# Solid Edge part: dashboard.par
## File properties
Author: Mac
Template: Normal.par
Last saved by: Mac
Revision: 6
Application: Solid Edge
Material: Epoxy, cast rigid
Face Style: Model Default
Fill Style: ANSI34(Plastic)
Virtual Style: Shiny resin yellow
Coef. of Thermal Exp: 5.9e-05
Thermal Conductivity: 2.1
Specific Heat: 0.0
Modulus of Elasticity: 3102640650.0
Poission's Ratio: 0.37
Yield Stress: 65500191.5
Ultimate Stress: 0.0
Elongation: 0.0
Density: 1300,000 kg/m^3
Accuracy: 0,990
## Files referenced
..\Asm16.asm
AC:\Documents and Settings\Mac\Desktop\ihu\Copy of paat4\Asm16.asm
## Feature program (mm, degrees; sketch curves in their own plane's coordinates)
sketch for "unnamed Protrusion 1" plane through (0, 0, 0) normal (0, 0, 1) x-axis (1, 0, 0)
  line (0, 0) -> (0, 27.8842)
  line (0, 27.8842) -> (0.9634, 27.8296)
  line (0.9634, 27.8296) -> (0.9634, 27.7356)
  line (17.9828, 26.6287) -> (17.9828, 25.9766)
  bspline degree 3 poles (17.9828, 25.9766) (24.7445, 25.4284) (31.4935, 24.7435) (38.2179, 23.8654) knots 0 1 multiplicities 4 4
  bspline degree 3 poles (38.2179, 23.8654) (40.5774, 20.624) (42.3706, 16.8932) (43.6319, 13.0202) (43.9649, 11.9978) (44.2696, 10.9289) (44.8221, 8.7743) (45.0694, 7.6895) (45.511, 5.5057) (45.7053, 4.4074) (45.87, 3.3016) (46.0334, 2.2045) (46.1675, 1.1039) (46.2626, 0) knots 0 0.5088 0.5836 0.6583 0.7331 1 multiplicities 4 3 2 2 3 4
  line (0, 0) -> (46.2626, 0)
extrude "unnamed Protrusion 1" add finite 17.53 along +normal
sketch for "unnamed Cutout 1" plane through (23.1313, 0, 8.765) normal (0, -1, 0) x-axis (1, 0, 0)
  line (-21.6003, 8.735) -> (-23.1313, -8.765)
  line (-23.1313, -8.765) -> (-27.6404, -8.765)
  line (-27.6404, -8.765) -> (-27.6404, 10.6782)
  line (-27.6404, 10.6782) -> (-21.6003, 10.6782)
  line (-21.6003, 10.6782) -> (-21.6003, 8.735)
extrude "unnamed Cutout 1" cut through along -normal
body pattern "unnamed BodyPattern 1"
pattern "unnamed Pattern 1"
swept protrusion "unnamed SweptProtrusion 1"
sketch for "unnamed Cutout 2" #1 plane through (18.5247, 0, 17.53) normal (0, 0, 1) x-axis (0, -1, 0)
  line (-3.3016, 27.3453) -> (-3.3016, 29.939)
  line (-3.3016, 29.939) -> (-31.4659, 29.939)
  line (-31.4659, 29.939) -> (-31.4659, -0.5419)
  line (-31.4659, -0.5419) -> (-25.9766, -0.5419)
sketch for "unnamed Cutout 2" #2 plane through (18.5247, 0, 17.53) normal (0, 0, 1) x-axis (0, -1, 0)
  line (3.3016, 27.3453) -> (3.3016, 29.939)
  line (3.3016, 29.939) -> (34.8167, 29.939)
  line (34.8167, -0.5419) -> (34.8167, 29.939)
  line (25.9766, -0.5419) -> (34.8167, -0.5419)
extrude "unnamed Cutout 2" cut through along -normal
sketch for "unnamed Cutout 3" plane through (18.5247, 0, 17.53) normal (0, 0, 1) x-axis (0, -1, 0)
  line (9.3717, -18.5247) -> (-5.6283, -18.5247)
  line (-5.6283, -2.5247) -> (-5.6283, -18.5247)
  arc centre (-4.6283, -2.5247) radius 1 from (-4.6283, -1.5247) to (-5.6283, -2.5247) ccw
  line (-4.6283, -1.5247) -> (8.3717, -1.5247)
  arc centre (8.3717, -2.5247) radius 1 from (8.3717, -1.5247) to (9.3717, -2.5247) cw
  line (9.3717, -2.5247) -> (9.3717, -18.5247)
extrude "unnamed Cutout 3" cut finite 1.4 along -normal
sketch for "ExtrudedCutout_5" plane through (0.647, 0, 7.3957) normal (-0.996195, 0, 0.087156) x-axis (0, -1, 0)
  line (-5.6283, 11.521) -> (8.3717, 11.521)
  line (-5.6283, -7.424) -> (-5.6283, 11.521)
  line (9.3717, -7.424) -> (-5.6283, -7.424)
  line (9.3717, 11.4338) -> (9.3717, -7.424)
extrude "ExtrudedCutout_5" cut finite 1.4 along -normal
fillet "Round_2" radius 1.4
sketch for "unnamed Cutout 4" plane through (18.5247, 0, 17.53) normal (0, 0, 1) x-axis (0, -1, 0)
  line (-23.0443, -3.5247) -> (-9.4443, -3.5247)
  arc centre (-9.4443, -3.7247) radius 0.2 from (-9.4443, -3.5247) to (-9.2443, -3.7247) cw
  line (-9.2443, -3.7247) -> (-9.2443, -17.2969)
  line (-23.2443, -17.2969) -> (-9.2443, -17.2969)
  line (-23.2443, -3.7247) -> (-23.2443, -17.2969)
  arc centre (-23.0443, -3.7247) radius 0.2 from (-23.0443, -3.5247) to (-23.2443, -3.7247) ccw
extrude "unnamed Cutout 4" cut along +normal
fillet "Round_6" radius 1
sketch for "ExtrudedProtrusion_4" plane through (17.134, 0, 18.2111) normal (-0.043619, 0, 0.999048) x-axis (0, -1, 0)
  line (23.9766, 1.0362) -> (23.9766, -14.6997)
  line (9.3717, -14.6997) -> (23.9766, -14.6997)
  line (9.3717, -14.6997) -> (9.3717, 1.0362)
  line (9.3717, 1.0362) -> (23.9766, 1.0362)
extrude "ExtrudedProtrusion_4" add along -normal
sketch for "ExtrudedProtrusion_5" plane through (18.0599, -16.6742, 17.9096) normal (0.953717, 0, -0.300706) x-axis (0, -1, 0)
  line (-7.3025, 0.3197) -> (-7.3025, -0.8635)
  arc centre (-5.8025, -0.8635) radius 1.5 from (-7.3025, -0.8635) to (-5.8025, -2.3635) ccw
  line (-5.8025, -2.3635) -> (5.8025, -2.3635)
  arc centre (5.8025, -0.8635) radius 1.5 from (7.3025, -0.8635) to (5.8025, -2.3635) cw
  line (7.3025, 0.3197) -> (7.3025, -0.8635)
  line (-7.3025, 0.3197) -> (7.3025, 0.3197)
extrude "ExtrudedProtrusion_5" add finite 14.4612 along +normal
fillet "Round_7" radius 0.5
sketch for "unnamed Cutout 5" plane through (9.8515, -16.6742, 17.8932) normal (-0.043619, 0, 0.999048) x-axis (0, -1, 0)
  line (-4.8025, 5.6717) -> (4.1975, 5.6717)
  arc centre (4.1975, 5.1717) radius 0.5 from (4.1975, 5.6717) to (4.6975, 5.1717) cw
  line (4.6975, 5.1717) -> (4.6975, -3.8283)
  arc centre (4.1975, -3.8283) radius 0.5 from (4.6975, -3.8283) to (4.1975, -4.3283) cw
  line (4.1975, -4.3283) -> (-4.8025, -4.3283)
  arc centre (-4.8025, -3.8283) radius 0.5 from (-4.8025, -4.3283) to (-5.3025, -3.8283) cw
  line (-5.3025, -3.8283) -> (-5.3025, 5.1717)
  arc centre (-4.8025, 5.1717) radius 0.5 from (-4.8025, 5.6717) to (-5.3025, 5.1717) ccw
extrude "unnamed Cutout 5" cut finite 1 along -normal
fillet "Round_4" radius 0.2
sketch for "ExtrudedProtrusion_6" plane through (2.9122, -16.6742, 24.084) normal (-0.953717, 0, 0.300706) x-axis (0, -1, 0)
  line (-0.8, -5.6945) -> (0.8, -5.6945)
  arc centre (0.8, -5.8945) radius 0.2 from (0.8, -5.6945) to (1, -5.8945) cw
  line (1, -5.8945) -> (1, -7.4945)
  arc centre (0.8, -7.4945) radius 0.2 from (1, -7.4945) to (0.8, -7.6945) cw
  line (0.8, -7.6945) -> (-0.8, -7.6945)
  arc centre (-0.8, -7.4945) radius 0.2 from (-0.8, -7.6945) to (-1, -7.4945) cw
  line (-1, -7.4945) -> (-1, -5.8945)
  arc centre (-0.8, -5.8945) radius 0.2 from (-0.8, -5.6945) to (-1, -5.8945) ccw
extrude "ExtrudedProtrusion_6" add finite 4.0043 along -normal  Profile_Plane1_Distance = 16.3033 mm
fillet "Round_8" radius 0.2
fillet "Round_9" radius 0.2
fillet "Round_11" radius 0.2
fillet "Round_14" radius 0.2
fillet "Round_15" radius 0.2
fillet "Round_16" radius 0.2
thinwall "Thinwall_6"  Thickness = 0.03 mm
sketch used by "unnamed Cutout 6" plane through (18.4609, -16.6742, 19.1814) normal (-0.953717, 0, 0.300706) x-axis (0, -1, 0)
extrude "unnamed Cutout 6" cut through along -normal
sketch for "unnamed Cutout 7" plane through (0.8991, -16.6742, 17.6993) normal (-0.953717, 0, 0.300706) x-axis (0, -1, 0)
  circle centre (0, 0) radius 0.75
extrude "unnamed Cutout 7" cut through along -normal
Other named dimensions: "ExtrudedSurface_1": FiniteDepth = 22.5828 mm | "ExtrudedSurface_2": FiniteDepth = 2.9872 mm | "ExtrudedSurface_3": FiniteDepth = 31.1007 mm
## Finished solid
Body 1: sheet body, 2 faces, 7 edges, 6 vertices.
  Faces by surface: plane 2
  Edges by curve: line 7
Body 2: sheet body, 1 face, 4 edges, 4 vertices.
  Faces by surface: swept 1
  Edges by curve: line 2, spline 2
Body 3: sheet body, 1 face, 4 edges, 4 vertices.
  Faces by surface: swept 1
  Edges by curve: line 2, spline 2
Body 4: solid body, 288 faces, 687 edges, 400 vertices.
  Faces by surface: cylinder 117, plane 65, torus 48, blend 34, sphere 10, swept 8, offset 3, spline 3
  Edges by curve: line 289, circle 266, intersection 77, ellipse 38, spline 12, curve on surface 5
Bounding box of the edges (mm; curved faces can reach further): 46.263 x 58.985 x 20.517, from (0, -27.8842, 0) to (46.2626, 31.1007, 20.5172).
Cylindrical faces by radius (mm): R0.17 x26, R0.2 x42, R0.23 x16, R0.47 x2, R0.5 x6, R0.53 x4, R0.75 x1, R0.97 x4, R1 x6, R1.03 x2, R1.3 x2, R1.4 x2, R1.47 x2, R1.5 x2
Toroidal faces (ring radius, tube radius in mm): R0.3 r0.17 x1, R0.3 r0.2 x5, R0.3 r0.23 x4, R0.4 r0.17 x4, R0.4 r0.2 x4, R0.7 r0.17 x4, R0.7 r0.2 x6, R0.7 r0.23 x2, R0.8 r0.17 x3, R0.8 r0.2 x3, R1.2 r0.17 x2, R1.2 r0.2 x4, R1.2 r0.23 x2, R1.3 r0.17 x2, R1.3 r0.2 x2
Spherical faces by radius (mm): R0.17 x4, R0.2 x5, R0.23 x1
Planar faces by outward normal: +x 6, +y 10, +z 2, -x 2, -y 10, -z 5, oblique 30
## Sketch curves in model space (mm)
line (18.2114, -9.5717, 18.3899) -> (18.2114, -23.7766, 18.3899)
line (18.2114, -23.7766, 18.3899) -> (18.3196, -23.7766, 18.7332)
arc centre (18.3196, -22.4766, 18.7332) radius 1.3 from (18.3196, -23.7766, 18.7332) through (18.6039, -23.3687, 19.635) to (18.7105, -22.4766, 19.973)
line (18.7105, -22.4766, 19.973) -> (18.7105, -10.8717, 19.973)
arc centre (18.3196, -10.8717, 18.7332) radius 1.3 from (18.7105, -10.8717, 19.973) through (18.5879, -9.9261, 19.584) to (18.3196, -9.5717, 18.7332)
line (18.3196, -9.5717, 18.7332) -> (18.2114, -9.5717, 18.3899)
line (4.2827, 0, 14.53) -> (21.6068, 0, 15.7292)
line (0.7738, 0, 16.1411) -> (4.2827, 0, 14.53)
line (42.2625, 0.0663, 17.4326) -> (32.6198, 0.0491, 17.4326)
line (32.729, 0.0484, 18.6804) -> (32.6198, 0.0491, 17.4326)
arc centre (32.7788, 0.0485, 18.6761) radius 0.05 from (32.7792, 0.0485, 18.7261) through (32.7441, 0.0484, 18.712) to (32.729, 0.0484, 18.6804)
spline (32.7792, 0.0485, 18.7261) -> (37.1438, 0.0564, 18.49) -> (42.2625, 0.0663, 17.4326)
spline (17.9828, 25.1295, 17.53) -> (17.9828, 0.2369, 18.7265) -> (17.9828, -24.9385, 17.53)
spline (28.2179, 25.034, 17.53) -> (32.7331, -0.0751, 17.53) -> (28.2179, -25.034, 17.53)
spline (0.9624, 27.7357, 11) -> (1.2467, 27.7213, 14.25) -> (1.5311, 27.7068, 17.5)
line (0.9624, 27.8365, 11) -> (0.9624, 27.7357, 11)
line (0, 0, 0) -> (0, 27.8842, 0)
spline (0, 27.8842, 0) -> (0.4812, 27.8606, 5.5) -> (0.9624, 27.8365, 11)
spline (0.0087, 27.783, 17.5) -> (9.1969, 27.265, 17.5) -> (17.9828, 26.6287, 17.5)
line (17.9828, 26.6287, 17.5) -> (17.9828, 25.9766, 17.5)
spline (17.9828, 25.9766, 17.5) -> (26.9212, 25.1666, 17.5) -> (35.8387, 24.168, 17.5)
spline (35.8387, 24.168, 17.5) -> (42.2298, 11.8156, 17.5) -> (44.5561, 0, 17.5)
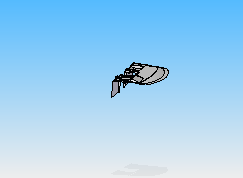
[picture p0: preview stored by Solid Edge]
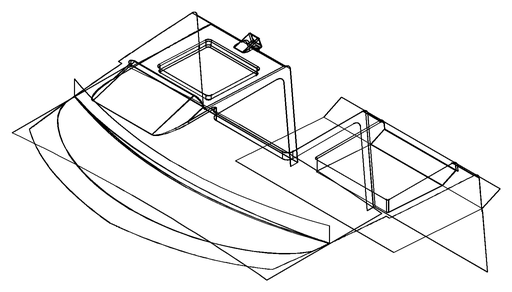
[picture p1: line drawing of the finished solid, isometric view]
